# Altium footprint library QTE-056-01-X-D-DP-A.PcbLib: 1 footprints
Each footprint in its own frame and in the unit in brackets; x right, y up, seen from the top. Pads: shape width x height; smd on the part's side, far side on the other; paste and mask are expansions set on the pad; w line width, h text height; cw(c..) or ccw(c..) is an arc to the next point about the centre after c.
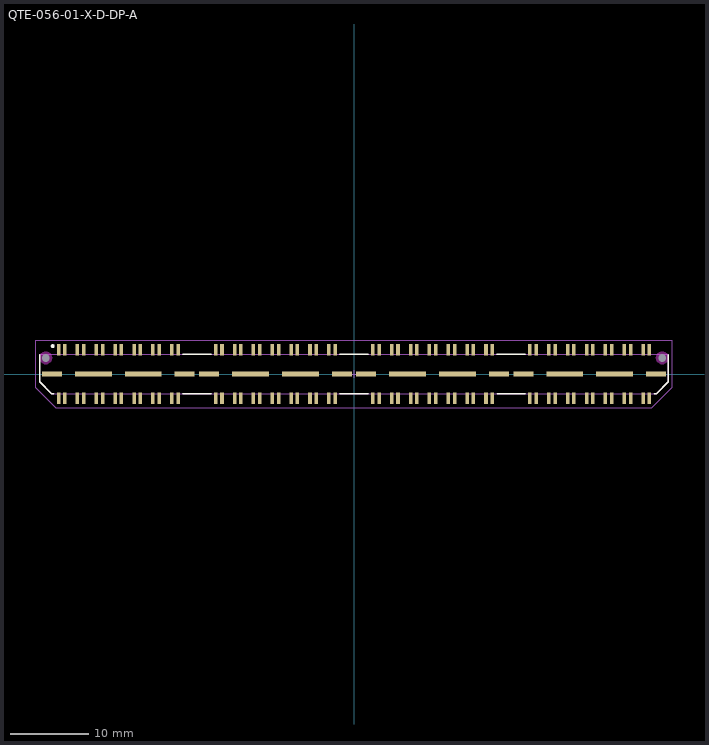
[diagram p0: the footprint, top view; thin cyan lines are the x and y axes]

## QTE-056-01-X-D-DP-A [mm] "0.80mm pitch, 112 pin, high speed terminal strip; differential"
height 4.27
pads (130):
  rect 0.45x1.45 smd mask+0: 1(-37.6,3.09) 2(-37.6,-3.09) 3(-36.8,3.09) 4(-36.8,-3.09) 5(-35.2,3.09) 6(-35.2,-3.09) 7(-34.4,3.09) 8(-34.4,-3.09) 9(-32.8,3.09) 10(-32.8,-3.09) 11(-32,3.09) 12(-32,-3.09) 13(-30.4,3.09) 14(-30.4,-3.09) 15(-29.6,3.09) 16(-29.6,-3.09) 17(-28,3.09) 18(-28,-3.09) 19(-27.2,3.09) 20(-27.2,-3.09) 21(-25.6,3.09) 22(-25.6,-3.09) 23(-24.8,3.09) 24(-24.8,-3.09) 25(-23.2,3.09) 26(-23.2,-3.09) 27(-22.4,3.09) 28(-22.4,-3.09) 29(-17.6,3.09) 30(-17.6,-3.09) 31(-16.8,3.09) 32(-16.8,-3.09) 33(-15.2,3.09) 34(-15.2,-3.09) 35(-14.4,3.09) 36(-14.4,-3.09) 37(-12.8,3.09) 38(-12.8,-3.09) 39(-12,3.09) 40(-12,-3.09) 41(-10.4,3.09) 42(-10.4,-3.09) 43(-9.6,3.09) 44(-9.6,-3.09) 45(-8,3.09) 46(-8,-3.09) 47(-7.2,3.09) 48(-7.2,-3.09) 49(-5.6,3.09) 50(-5.6,-3.09) 51(-4.8,3.09) 52(-4.8,-3.09) 53(-3.2,3.09) 54(-3.2,-3.09) 55(-2.4,3.09) 56(-2.4,-3.09) 57(2.4,3.09) 58(2.4,-3.09) 59(3.2,3.09) 60(3.2,-3.09) 61(4.8,3.09) 62(4.8,-3.09) 63(5.6,3.09) 64(5.6,-3.09) 65(7.2,3.09) 66(7.2,-3.09) 67(8,3.09) 68(8,-3.09) 69(9.6,3.09) 70(9.6,-3.09) 71(10.4,3.09) 72(10.4,-3.09) 73(12,3.09) 74(12,-3.09) 75(12.8,3.09) 76(12.8,-3.09) 77(14.4,3.09) 78(14.4,-3.09) 79(15.2,3.09) 80(15.2,-3.09) 81(16.8,3.09) 82(16.8,-3.09) 83(17.6,3.09) 84(17.6,-3.09) 85(22.4,3.09) 86(22.4,-3.09) 87(23.2,3.09) 88(23.2,-3.09) 89(24.8,3.09) 90(24.8,-3.09) 91(25.6,3.09) 92(25.6,-3.09) 93(27.2,3.09) 94(27.2,-3.09) 95(28,3.09) 96(28,-3.09) 97(29.6,3.09) 98(29.6,-3.09) 99(30.4,3.09) 100(30.4,-3.09) 101(32,3.09) 102(32,-3.09) 103(32.8,3.09) 104(32.8,-3.09) 105(34.4,3.09) 106(34.4,-3.09) 107(35.2,3.09) 108(35.2,-3.09) 109(36.8,3.09) 110(36.8,-3.09) 111(37.6,3.09) 112(37.6,-3.09)
  rect 2.55x0.65 smd mask+0: 113(-38.445,0) 116(-21.555,0) 117(-18.445,0) 120(-1.555,0) 121(1.555,0) 124(18.445,0) 125(21.555,0) 128(38.445,0)
  rect 4.7x0.65 smd mask+0: 114(-33.175,0) 115(-26.825,0) 118(-13.175,0) 119(-6.825,0) 122(6.825,0) 123(13.175,0) 126(26.825,0) 127(33.175,0)
  round 0.5 hole 1 unplated mask+0: 129(-39.24,2.04) 130(39.24,2.04)
Top Overlay:
  circle w0.25: c-38.35,3.55 r0.125
  lines w0.2: -40,2.45 -40,-1 -38.5,-2.5 -38.2,-2.5 ; -21.814,-2.501 -18.197,-2.501 ; -21.803,2.502 -18.191,2.502 ; -1.816,2.499 1.794,2.499 ; -1.809,-2.494 1.801,-2.494 ; 18.197,2.506 21.802,2.506 ; 18.208,-2.494 21.802,-2.494 ; 38.2,-2.5 38.5,-2.5 40,-1 40,2.45
Keep-Out Layer:
  pour cut-out: -38.433,2.04 -38.461,2.249 -38.541,2.443 -38.669,2.611 -38.837,2.739 -39.031,2.819 -39.24,2.847 -39.449,2.819 -39.643,2.739 -39.811,2.611 -39.939,2.443 -40.019,2.249 -40.047,2.04 -40.019,1.831 -39.939,1.637 -39.811,1.469 -39.643,1.341 -39.449,1.261 -39.24,1.233 -39.031,1.261 -38.837,1.341 -38.669,1.469 -38.541,1.637 -38.461,1.831
  pour cut-out: 40.047,2.04 40.019,2.249 39.939,2.443 39.811,2.611 39.643,2.739 39.449,2.819 39.24,2.847 39.031,2.819 38.837,2.739 38.669,2.611 38.541,2.443 38.461,2.249 38.433,2.04 38.461,1.831 38.541,1.637 38.669,1.469 38.837,1.341 39.031,1.261 39.24,1.233 39.449,1.261 39.643,1.341 39.811,1.469 39.939,1.637 40.019,1.831
Mechanical 13:
  lines w0.1: -40,-1 -38.5,-2.5 38.5,-2.5 40,-1 40,2.5 -40,2.5 -40,-1
  text ".Designator" at 0.254,0.254 h1.52
Mechanical 15:
  lines w0.05: -0.5,0 0.5,0 ; 0,-0.5 0,0.5 ; -40.5,-1.75 -37.95,-4.3 37.9,-4.3 40.5,-1.7 40.5,4.3 -40.5,4.3 -40.5,-1.75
